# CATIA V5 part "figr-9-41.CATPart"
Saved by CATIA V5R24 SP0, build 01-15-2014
Part number: Part1
Bounding box of the stored display mesh (mm): x -40 to 40, y -20.616 to 191.034, z 0 to 131.022
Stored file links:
  D:\KAVITA\CATIA V5-6R2014 Project_ Kavita\CATIA V5-6R2014_partfiles\Partfiles\c09_catia_v5-6r2014_prt\figr-9-41.CATPart
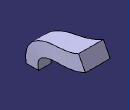
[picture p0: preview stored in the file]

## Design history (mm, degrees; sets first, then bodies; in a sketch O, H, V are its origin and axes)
Set1
  Plane1: type Normal, Curve Sketch2, RefPoint vertex of Sketch2
Body1 (main body)
  Sketch1 on xy-plane, origin (0, 0, 0), H (1, 0, 0), V (0, 1, 0)
    line L1 (20, 20) -> (20, -20)
    line L2 (20, -20) -> (-20, -20)
    line L3 (-20, -20) -> (-20, 20)
    line L4 (-20, 20) -> (20, 20)
    vertical: L1 V, L3 V
    horizontal: L2 H, L4 H
    equidistance: L1 L3 O, L2 L4 O
  Sketch2 on yz-plane, origin (0, 0, 0), H (0, 1, 0), V (0, 0, 1)
    spline S1 through (0, 0) (20, 60) (60, 80) (120, 90) (180, 110)
    point P1 (0, 0)
    coincidence: P1 O
  Sketch3 on Plane1, origin (0, 186.3865, 97.8327), H (1, 0, 0), V (0, -0.4648, 0.8854)
    point P1 (0, 13.7415)
    line L1 (40, 37.4831) -> (40, -10)
    line L2 (40, -10) -> (-40, -10)
    line L3 (-40, -10) -> (-40, 37.4831)
    line L4 (-40, 37.4831) -> (40, 37.4831)
    reference projected point E1 (0, 13.7415) from vertex of Sketch2
    coincidence: P1 V, P1 E1
    vertical: L1 V, L3 V
    horizontal: L2 H, L4 H
    equidistance: L1 L3 P1, L2 L4 P1
  Loft1: Sections (Sketch1; Sketch3), Spine Sketch2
